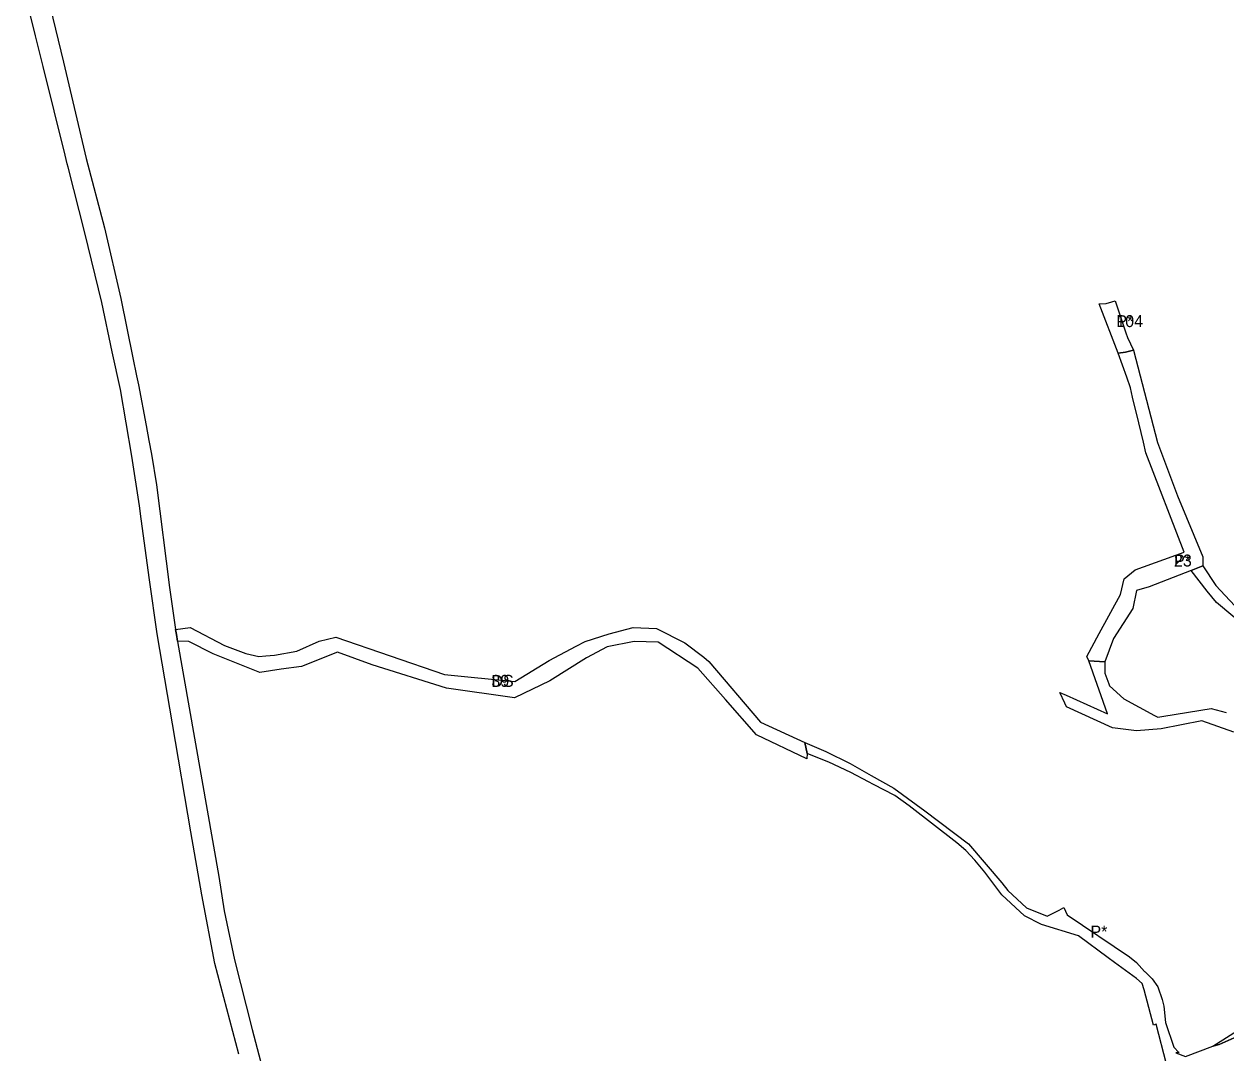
# Model space of a CAD drawing. Extents: x -501732 to -497665, y -1142022 to -1138283.
# Drawn here: x -499525 to -498822, y -1140303 to -1139701 of the extents above; entities that cross this region are included whole.
import ezdxf

# ---------------------------------------------------------------- set-up
doc = ezdxf.new("R2010")
doc.units = 0
for name, color, linetype in [('4', 7, 'Continuous'), ('43', 7, 'Continuous'), ('44', 7, 'Continuous'), ('5', 7, 'Continuous'), ('61', 7, 'Continuous')]:
    doc.layers.add(name, color=color, linetype=linetype)

msp = doc.modelspace()

# ---------------------------------------------------------------- linework, layer by layer
at = {"layer": '4'}
for points in [[(-499512.72, -1139678.22), (-499501.79, -1139723.41), (-499488.6, -1139779.78), (-499477.85, -1139820.49), (-499468.2, -1139861.8), (-499461.29, -1139896.43), (-499459.07, -1139907.03), (-499457.97, -1139912.29), (-499453.46, -1139936.13), (-499451.8, -1139944.91), (-499450.28, -1139952.9), (-499447.44, -1139970.83), (-499439.67, -1140030.91), (-499436.2, -1140055.59), (-499435.72, -1140058.5), (-499435.04, -1140062.59), (-499410.93, -1140200.05), (-499407.83, -1140220.19), (-499401.63, -1140248.76), (-499391.39, -1140289.65), (-499381.85, -1140325.93)], [(-499399.25, -1140304.07), (-499413.21, -1140251.05), (-499420.76, -1140210.69), (-499427.23, -1140173.93), (-499438.04, -1140110.7), (-499447.04, -1140058.09), (-499451.4, -1140026.47), (-499456.34, -1139990.7), (-499457.39, -1139983.06), (-499461.72, -1139954.06), (-499468.39, -1139915.13), (-499473.29, -1139892.94), (-499479.25, -1139864.2), (-499489.26, -1139823.41), (-499499.12, -1139784.95), (-499499.62, -1139783), (-499500.87, -1139777.93), (-499513.69, -1139725.93), (-499518.12, -1139708.11), (-499524.86, -1139681.02)], [(-498845.2, -1140305.46), (-498829.21, -1140299.26), (-498825.436, -1140298.332), (-498823.821, -1140297.619), (-498816.65, -1140294.45)]]:
    msp.add_lwpolyline(points, dxfattribs=at)
at = {"layer": '43'}
for points in [[(-498797.14, -1140064.74), (-498827.06, -1140039.73), (-498832.57, -1140033.12), (-498837.16, -1140027.05), (-498841.81, -1140020.91), (-498835.04, -1140018.3), (-498827.53, -1140029.8), (-498810.94, -1140047.51)], [(-498816.96, -1140115.59), (-498835.67, -1140109.02), (-498859.39, -1140113.63), (-498873.77, -1140114.75), (-498887.86, -1140113.07), (-498914.88, -1140100.8), (-498915.75, -1140098.62), (-498918.76, -1140092.27), (-498915.07, -1140093.96), (-498890.84, -1140104.93), (-498901.72, -1140073.76), (-498892.44, -1140074.41), (-498892.44, -1140080.98), (-498890.11, -1140087.23), (-498889.63, -1140088.52), (-498881.37, -1140096.14), (-498863.24, -1140105.91), (-498861.45, -1140106.87), (-498857.94, -1140106.31), (-498830.17, -1140101.82), (-498821.4, -1140104)], [(-498856.22, -1140309.93), (-498862.32, -1140286.49), (-498863.89, -1140286.98), (-498869.45, -1140266.34), (-498870.55, -1140262.61), (-498873.88, -1140259.72), (-498886.82, -1140250.31), (-498890.52, -1140247.57), (-498907.85, -1140234.83), (-498929.54, -1140228.06), (-498939.48, -1140223.14), (-498952.73, -1140210.75), (-498962.7, -1140197.47), (-498968.53, -1140190.48), (-498973.81, -1140184.76), (-498978.99, -1140180.31), (-499006.88, -1140158.7), (-499015.35, -1140152.69), (-499027.82, -1140146.11), (-499030.63, -1140144.63), (-499041.05, -1140139.24), (-499053.88, -1140133.07), (-499063.26, -1140129.4), (-499066.66, -1140128.07), (-499067.87, -1140121.71), (-499055.62, -1140126.94), (-499041.4, -1140133.93), (-499029.06, -1140140.85), (-499015.83, -1140148.28), (-499002.79, -1140157.85), (-498997.79, -1140161.63), (-498972.17, -1140180.98), (-498952.72, -1140203.84), (-498949.18, -1140208.16), (-498938.28, -1140218.36), (-498926.07, -1140223.28), (-498919.2, -1140219.69), (-498916.33, -1140218.2), (-498914.48, -1140222.39), (-498877.91, -1140247.09), (-498873.79, -1140250.36), (-498869.107, -1140255.545), (-498868.85, -1140255.83), (-498864.75, -1140260), (-498861.43, -1140264.7), (-498858.81, -1140271.94), (-498857.9, -1140275.91), (-498856.94, -1140285.41), (-498851.97, -1140299.97), (-498849.12, -1140302.98), (-498848.99, -1140303.04), (-498850.81, -1140303.29), (-498845.2, -1140305.46)], [(-498816.65, -1140294.45), (-498823.821, -1140297.619), (-498825.436, -1140298.332), (-498829.21, -1140299.26), (-498803.03, -1140282.74)]]:
    msp.add_lwpolyline(points, dxfattribs=at)
at = {"layer": '44'}
for points in [[(-498875.61, -1139892.022), (-498880.269, -1139893.115), (-498884.66, -1139893.79), (-498895.652, -1139864.947), (-498891.55, -1139864.77), (-498888.274, -1139863.756), (-498886.267, -1139863.135), (-498880.2, -1139881.87), (-498879.19, -1139884.66)], [(-498887.34, -1140060.75), (-498892.44, -1140074.41), (-498901.72, -1140073.76), (-498903.001, -1140071.354), (-498895.658, -1140057.771), (-498883.148, -1140035.055), (-498881.013, -1140025.941), (-498874.582, -1140020.642), (-498845.946, -1140010.201), (-498868.36, -1139952.17), (-498869.84, -1139945.93), (-498872.53, -1139934.58), (-498876.11, -1139919.46), (-498877.41, -1139913.99), (-498879.59, -1139907.91), (-498884.66, -1139893.79), (-498880.269, -1139893.115), (-498875.61, -1139892.022), (-498861.558, -1139946.004), (-498849.882, -1139977.206), (-498834.986, -1140013.038), (-498835.04, -1140018.3), (-498841.81, -1140020.91), (-498866.48, -1140030.53), (-498873.85, -1140032.72), (-498876.02, -1140043.2)]]:
    msp.add_lwpolyline(points, close=True, dxfattribs=at)
at = {"layer": '5'}
msp.add_lwpolyline([(-499395.09, -1140069.47), (-499387.43, -1140071.37), (-499383.4, -1140070.89), (-499378.26, -1140070.59), (-499365.32, -1140068.27), (-499352.11, -1140062.42), (-499342.49, -1140060.03), (-499278.75, -1140081.89), (-499237.69, -1140085.86), (-499217.66, -1140073.7), (-499201.81, -1140065.312), (-499196.59, -1140062.55), (-499182.39, -1140057.99), (-499168.46, -1140054.39), (-499154.67, -1140054.94), (-499138.08, -1140063.36), (-499126.98, -1140071.61), (-499124.2, -1140074.18), (-499093.87, -1140109.64), (-499067.87, -1140121.71), (-499066.66, -1140128.07), (-499066.754, -1140131.09), (-499096.327, -1140117.084), (-499114.288, -1140096.499), (-499130.635, -1140078.135), (-499153.784, -1140062.844), (-499167.819, -1140062.549), (-499183.644, -1140065.65), (-499195.655, -1140072.143), (-499217.207, -1140085.546), (-499237.76, -1140095.541), (-499277.693, -1140089.924), (-499321.12, -1140076.23), (-499341.338, -1140068.845), (-499362.445, -1140077.078), (-499374.338, -1140078.803), (-499386.795, -1140080.608), (-499414.175, -1140069.801), (-499428.433, -1140062.48), (-499435.083, -1140062.329), (-499435.72, -1140058.5), (-499436.2, -1140055.59), (-499427.56, -1140054.34), (-499407.57, -1140064.91)], close=True, dxfattribs=at)

# ---------------------------------------------------------------- texts
at = {"layer": '43'}
msp.add_text('P*', height=7, dxfattribs=at).set_placement((-498900.8, -1140235.768))
at = {"layer": '44'}
for p in [(-498885.691, -1139878.514), (-498851.922, -1140018.637)]:
    msp.add_text('P*', height=7, rotation=359.497417, dxfattribs=at).set_placement(p)
at = {"layer": '5'}
msp.add_text('DS', height=7, dxfattribs=at).set_placement((-499251.345, -1140089.069))
at = {"layer": '61'}
for s, p in [('104', (-498885.662, -1139878.514)), ('23', (-498851.922, -1140018.637)), ('39', (-499251.362, -1140089.069))]:
    msp.add_text(s, height=7, dxfattribs=at).set_placement(p)

doc.saveas('drawing.dxf')
